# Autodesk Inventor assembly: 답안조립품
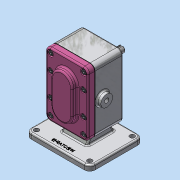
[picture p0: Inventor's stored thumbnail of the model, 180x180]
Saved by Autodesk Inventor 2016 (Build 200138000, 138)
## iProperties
Created: 2020-04
Part Number: 답안조립품
Material: 일반
Document SubType Name: Assembly
Designer: Administrator
Author: Administrator
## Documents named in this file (11)
- C:\Users\Administrator\Desktop\700407V1018\답안조립품.iam
- C:\Users\Administrator\Desktop\700407V1018\본체.ipt
- C:\Users\Administrator\Desktop\700407V1018\베어링부시.ipt
- C:\Users\Administrator\Desktop\700407V1018\메인축.ipt
- C:\Users\Administrator\Desktop\700407V1018\키 6 x 6 x 18.ipt
- C:\Users\Administrator\Desktop\700407V1018\서브축.ipt
- C:\Users\Administrator\Desktop\700407V1018\스퍼기어.ipt
- C:\Users\Administrator\Desktop\700407V1018\개스킷.ipt
- C:\Users\Administrator\Desktop\700407V1018\커버.ipt
- C:\Users\Administrator\Desktop\700407V1018\오일 실 16 28 7.ipt
- C:\Users\Administrator\Desktop\700407V1018\볼트 M5.ipt
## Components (1 placed, 1 different names)
1. 개스킷:1
